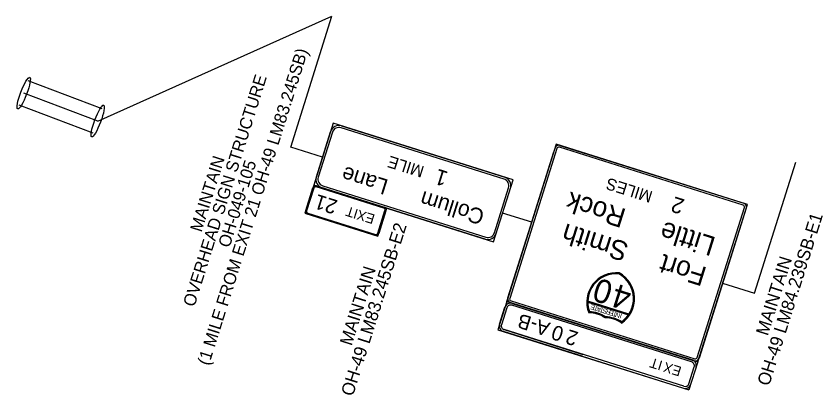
# Model space of a CAD drawing. Extents: x 641128 to 649424, y 422807 to 432853.
# Drawn here: x 644868 to 645659, y 432481 to 432853 of the extents above; entities that cross this region are included whole.
import ezdxf

# ---------------------------------------------------------------- set-up
doc = ezdxf.new("R2010")
doc.units = 0
for name, color, linetype in [('C-TRAF-SYMB', 7, 'Continuous'), ('Default', 7, 'Continuous'), ('R_Dimension', 7, 'Continuous'), ('S_SIGN', 7, 'Continuous')]:
    doc.layers.add(name, color=color, linetype=linetype)

msp = doc.modelspace()

# ---------------------------------------------------------------- linework, layer by layer
at = {"layer": 'C-TRAF-SYMB'}
for p, q in [((644952.5, 432761.81), (644879.93, 432789.25)), ((644947.97, 432749.84), (644875.41, 432777.27)), ((644943.44, 432737.87), (644870.88, 432765.3))]:
    msp.add_line(p, q, dxfattribs=at)
for centre in [(644875.41, 432777.27), (644947.97, 432749.84)]:
    msp.add_ellipse(centre, major_axis=(-5.88, -15.56), ratio=0.180134, dxfattribs=at)
at = {"layer": 'Default'}
for p, q in [((645355.46, 432692.11), (645355.46, 432692.11)), ((645337.13, 432640.29), (645351.02, 432684.42)), ((645337.13, 432640.29), (645337.13, 432640.29))]:
    msp.add_line(p, q, dxfattribs=at)
at = {"layer": 'S_SIGN'}
for p, q in [((644947.97, 432749.84), (645177.77, 432852.82)), ((645178.96, 432747.69), (645159.86, 432687.02)), ((645355.46, 432692.11), (645178.96, 432747.69)), ((645187.24, 432745.08), (645347.19, 432694.72)), ((645187.24, 432745.08), (645347.19, 432694.72)), ((645162.46, 432695.29), (645176.36, 432739.42)), ((645162.46, 432695.29), (645176.36, 432739.42)), ((645178.2, 432738.84), (645164.3, 432694.71)), ((645178.2, 432738.84), (645164.3, 432694.71)), ((645178.2, 432738.84), (645178.2, 432738.84)), ((645178.2, 432738.84), (645178.2, 432738.84)), ((645346.61, 432692.88), (645186.66, 432743.25)), ((645346.61, 432692.88), (645186.66, 432743.25)), ((645397.78, 432727.08), (645349.15, 432572.64)), ((645397.78, 432727.08), (645349.15, 432572.64)), ((645350.31, 432576.32), (645396.62, 432723.41)), ((645350.31, 432576.32), (645396.62, 432723.41)), ((645350.31, 432576.32), (645396.62, 432723.41)), ((645398.46, 432722.83), (645352.15, 432575.74)), ((645398.46, 432722.83), (645352.15, 432575.74)), ((645398.46, 432722.83), (645352.15, 432575.74)), ((645398.46, 432722.83), (645352.15, 432575.74)), ((645585.31, 432668.03), (645397.78, 432727.08)), ((645398.46, 432722.83), (645398.46, 432722.83)), ((645398.46, 432722.83), (645398.46, 432722.83)), ((645581.06, 432667.35), (645400.88, 432724.09)), ((645581.06, 432667.35), (645400.88, 432724.09)), ((645401.46, 432725.93), (645581.64, 432669.19)), ((645401.46, 432725.93), (645581.64, 432669.19)), ((645349.15, 432572.64), (645395.46, 432719.73)), ((645336.36, 432631.44), (645355.46, 432692.11)), ((645346.61, 432692.88), (645346.61, 432692.88)), ((645346.61, 432692.88), (645346.61, 432692.88)), ((645159.86, 432687.02), (645151.17, 432659.44)), ((645152.04, 432662.2), (645158.99, 432684.26)), ((645152.04, 432662.2), (645158.99, 432684.26)), ((645159.91, 432683.97), (645152.96, 432661.91)), ((645159.91, 432683.97), (645152.96, 432661.91)), ((645159.86, 432687.02), (645336.36, 432631.44)), ((645231.56, 432664.44), (645159.86, 432687.02)), ((645159.91, 432683.97), (645159.91, 432683.97)), ((645159.91, 432683.97), (645159.91, 432683.97)), ((645228.51, 432664.39), (645162.33, 432685.23)), ((645228.51, 432664.39), (645162.33, 432685.23)), ((645162.62, 432686.15), (645228.8, 432665.31)), ((645162.62, 432686.15), (645228.8, 432665.31)), ((645328.09, 432634.04), (645168.13, 432684.41)), ((645328.09, 432634.04), (645168.13, 432684.41)), ((645168.71, 432686.25), (645328.66, 432635.88)), ((645168.71, 432686.25), (645168.71, 432686.25)), ((645168.71, 432686.25), (645328.66, 432635.88)), ((645168.71, 432686.25), (645168.71, 432686.25)), ((645337.13, 432640.29), (645351.02, 432684.42)), ((645536.68, 432513.59), (645585.31, 432668.03)), ((645581.06, 432667.35), (645581.06, 432667.35)), ((645581.06, 432667.35), (645581.06, 432667.35)), ((645585.31, 432668.03), (645585.31, 432668.03)), ((645151.17, 432659.44), (645222.88, 432636.86)), ((645220.12, 432637.73), (645153.93, 432658.57)), ((645220.12, 432637.73), (645153.93, 432658.57)), ((645154.22, 432659.49), (645220.41, 432638.65)), ((645154.22, 432659.49), (645154.22, 432659.49)), ((645154.22, 432659.49), (645220.41, 432638.65)), ((645154.22, 432659.49), (645154.22, 432659.49)), ((645222.83, 432639.91), (645229.77, 432661.97)), ((645222.83, 432639.91), (645229.77, 432661.97)), ((645222.88, 432636.86), (645231.56, 432664.44)), ((645230.69, 432661.68), (645223.75, 432639.62)), ((645230.69, 432661.68), (645223.75, 432639.62)), ((645228.51, 432664.39), (645228.51, 432664.39)), ((645228.51, 432664.39), (645228.51, 432664.39)), ((645231.56, 432664.44), (645231.56, 432664.44)), ((645373.68, 432650.55), (645345.2, 432659.52)), ((645536, 432517.85), (645582.32, 432664.93)), ((645536, 432517.85), (645582.32, 432664.93)), ((645584.16, 432664.35), (645537.84, 432517.27)), ((645584.16, 432664.35), (645537.84, 432517.27)), ((645222.83, 432639.91), (645222.83, 432639.91)), ((645222.83, 432639.91), (645222.83, 432639.91)), ((645459.63, 432600.88), (645459.16, 432600.04)), ((645459.63, 432600.88), (645459.16, 432600.04)), ((645459.63, 432600.88), (645459.16, 432600.04)), ((645459.63, 432600.88), (645459.16, 432600.04)), ((645459.53, 432599.92), (645459.63, 432600.88)), ((645459.53, 432599.92), (645459.63, 432600.88)), ((645459.53, 432599.92), (645459.63, 432600.88)), ((645459.53, 432599.92), (645459.63, 432600.88)), ((645349.15, 432572.64), (645340.47, 432545.07)), ((645349.15, 432572.64), (645536.68, 432513.59)), ((645420.85, 432550.07), (645349.15, 432572.64)), ((645533, 432514.75), (645352.83, 432571.49)), ((645353.41, 432573.33), (645533.58, 432516.59)), ((645353.41, 432573.33), (645353.41, 432573.33)), ((645353.41, 432573.33), (645533.58, 432516.59)), ((645353.41, 432573.33), (645353.41, 432573.33)), ((645437.4, 432544.86), (645354.66, 432570.91)), ((645354.66, 432570.91), (645531.17, 432515.33)), ((645354.66, 432570.91), (645531.17, 432515.33)), ((645428.71, 432573.23), (645428.42, 432572.31)), ((645428.71, 432573.23), (645428.42, 432572.31)), ((645428.71, 432573.23), (645428.42, 432572.31)), ((645428.71, 432573.23), (645428.42, 432572.31)), ((645428.42, 432572.31), (645468.84, 432559.58)), ((645428.42, 432572.31), (645468.84, 432559.58)), ((645428.42, 432572.31), (645468.84, 432559.58)), ((645428.42, 432572.31), (645468.84, 432559.58)), ((645428.69, 432572.23), (645468.57, 432559.67)), ((645428.69, 432572.23), (645468.57, 432559.67)), ((645469.13, 432560.5), (645428.71, 432573.23)), ((645469.13, 432560.5), (645428.71, 432573.23)), ((645469.13, 432560.5), (645428.71, 432573.23)), ((645469.13, 432560.5), (645428.71, 432573.23)), ((645469.13, 432560.5), (645428.71, 432573.23)), ((645469.13, 432560.5), (645428.71, 432573.23)), ((645530.59, 432513.49), (645354.09, 432569.07)), ((645429.63, 432562.79), (645429.62, 432561.83)), ((645429.63, 432562.79), (645429.62, 432561.83)), ((645429.63, 432562.79), (645429.62, 432561.83)), ((645429.63, 432562.79), (645429.62, 432561.83)), ((645429.62, 432561.83), (645430.52, 432562.17)), ((645429.62, 432561.83), (645430.52, 432562.17)), ((645429.62, 432561.83), (645430.52, 432562.17)), ((645429.62, 432561.83), (645430.52, 432562.17)), ((645445.75, 432557.72), (645445.74, 432556.76)), ((645445.75, 432557.72), (645445.74, 432556.76)), ((645445.75, 432557.72), (645445.74, 432556.76)), ((645445.75, 432557.72), (645445.74, 432556.76)), ((645445.74, 432556.76), (645446.28, 432557.55)), ((645445.74, 432556.76), (645446.28, 432557.55)), ((645445.74, 432556.76), (645446.28, 432557.55)), ((645445.74, 432556.76), (645446.28, 432557.55)), ((645468.84, 432559.58), (645469.13, 432560.5)), ((645468.84, 432559.58), (645469.13, 432560.5)), ((645468.84, 432559.58), (645469.13, 432560.5)), ((645468.84, 432559.58), (645469.13, 432560.5)), ((645469.13, 432560.5), (645469.13, 432560.5)), ((645469.13, 432560.5), (645469.13, 432560.5)), ((645461.31, 432552.48), (645461.85, 432551.68)), ((645461.31, 432552.48), (645461.85, 432551.68)), ((645461.31, 432552.48), (645461.85, 432551.68)), ((645461.31, 432552.48), (645461.85, 432551.68)), ((645461.85, 432551.68), (645462.4, 432552.47)), ((645461.85, 432551.68), (645462.4, 432552.47)), ((645461.85, 432551.68), (645462.4, 432552.47)), ((645461.85, 432551.68), (645462.4, 432552.47)), ((645340.47, 432545.07), (645528, 432486.01)), ((645346.56, 432545.17), (645423.78, 432520.85)), ((645523.06, 432489.59), (645346.56, 432545.17)), ((645437.4, 432544.86), (645437.4, 432544.86)), ((645423.2, 432519.01), (645528, 432486.01)), ((645536, 432517.85), (645536, 432517.85)), ((645536, 432517.85), (645536, 432517.85)), ((645536.68, 432513.59), (645528, 432486.01))]:
    msp.add_line(p, q, dxfattribs=at)
for points in [[(645168.48, 432714.41), (645137.28, 432724.24), (645177.77, 432852.82)], [(645561, 432590.81), (645592.2, 432580.99), (645632.69, 432709.57)], [(645342.2, 432550.58), (645347.41, 432567.13)], [(645349.25, 432566.55), (645344.04, 432550)], [(645349.25, 432566.55), (645349.25, 432566.55), (645349.25, 432566.55)], [(645423.2, 432519.01), (645345.98, 432543.33)], [(645346.56, 432545.17), (645423.78, 432520.85)], [(645346.56, 432545.17), (645346.56, 432545.17), (645346.56, 432545.17)], [(645527.9, 432492.11), (645533.11, 432508.66)]]:
    msp.add_lwpolyline(points, dxfattribs=at)
for centre, radius, start, end in [((645184.63, 432736.81), 8.67, 72.52135, 162.52135), ((645184.63, 432736.81), 8.67, 72.52135, 162.52135), ((645184.63, 432736.81), 6.75, 72.52135, 162.52135), ((645184.63, 432736.81), 6.75, 72.52135, 162.52135), ((645400.3, 432722.25), 3.86, 72.52135, 162.52135), ((645400.3, 432722.25), 3.86, 72.52135, 162.52135), ((645400.3, 432722.25), 1.93, 72.52135, 162.52135), ((645400.3, 432722.25), 1.93, 72.52135, 162.52135), ((645170.74, 432692.69), 8.67, 162.52134, 252.52134), ((645170.74, 432692.69), 8.67, 162.52134, 252.52134), ((645170.74, 432692.69), 6.75, 162.52134, 252.52134), ((645170.74, 432692.69), 6.75, 162.52134, 252.52134), ((645344.59, 432686.44), 6.75, 342.52134, 72.52135), ((645344.59, 432686.44), 6.75, 342.52134, 72.52135), ((645344.59, 432686.44), 8.67, 342.52134, 72.52135), ((645344.59, 432686.44), 8.67, 342.52134, 72.52135), ((645161.75, 432683.39), 2.89, 72.52135, 162.52135), ((645161.75, 432683.39), 2.89, 72.52135, 162.52135), ((645161.75, 432683.39), 1.93, 72.52135, 162.52135), ((645161.75, 432683.39), 1.93, 72.52135, 162.52135), ((645580.48, 432665.51), 1.93, 342.52134, 72.52135), ((645580.48, 432665.51), 1.93, 342.52134, 72.52135), ((645580.48, 432665.51), 3.86, 342.52134, 72.52135), ((645580.48, 432665.51), 3.86, 342.52134, 72.52135), ((645154.8, 432661.33), 2.89, 162.52134, 252.52134), ((645154.8, 432661.33), 2.89, 162.52134, 252.52134), ((645154.8, 432661.33), 1.93, 162.52134, 252.52134), ((645154.8, 432661.33), 1.93, 162.52134, 252.52134), ((645227.93, 432662.55), 1.93, 342.52134, 72.52135), ((645227.93, 432662.55), 1.93, 342.52134, 72.52135), ((645227.93, 432662.55), 2.89, 342.52134, 72.52135), ((645227.93, 432662.55), 2.89, 342.52134, 72.52135), ((645220.99, 432640.49), 2.89, 252.52134, 342.52134), ((645220.99, 432640.49), 2.89, 252.52134, 342.52134), ((645220.99, 432640.49), 1.93, 252.52134, 342.52134), ((645220.99, 432640.49), 1.93, 252.52134, 342.52134), ((645330.69, 432642.32), 8.67, 252.52134, 342.52134), ((645330.69, 432642.32), 8.67, 252.52134, 342.52134), ((645330.69, 432642.32), 6.75, 252.52134, 342.52134), ((645330.69, 432642.32), 6.75, 252.52134, 342.52134), ((645456.64, 432572.12), 28.91, 84.05832, 200.8524), ((645456.64, 432572.12), 28.91, 84.0583, 200.85241), ((645456.64, 432572.12), 28.91, 84.0583, 200.85241), ((645456.64, 432572.12), 28.91, 84.05832, 200.8524), ((645456.64, 432572.12), 28.91, 84.0583, 200.85241), ((645456.64, 432572.12), 28.91, 84.0583, 200.85241), ((645456.64, 432572.12), 27.95, 84.0583, 200.85241), ((645456.64, 432572.12), 27.95, 84.0583, 200.85241), ((645456.64, 432572.12), 27.95, 84.0583, 200.85241), ((645456.64, 432572.12), 27.95, 84.0583, 200.85241), ((645456.64, 432572.14), 27.95, 84.4508, 177.76811), ((645456.64, 432572.14), 27.95, 84.4508, 177.76811), ((645445.61, 432575.6), 27.95, 304.1903, 60.9844), ((645445.61, 432575.6), 27.95, 304.1903, 60.9844), ((645445.61, 432575.6), 27.95, 304.1903, 60.9844), ((645445.61, 432575.6), 27.95, 304.1903, 60.9844), ((645445.62, 432575.61), 27.95, 327.27459, 60.59192), ((645445.62, 432575.61), 27.95, 327.27459, 60.59192), ((645445.61, 432575.6), 28.91, 304.1903, 60.9844), ((645445.61, 432575.6), 28.91, 304.1903, 60.9844), ((645445.61, 432575.6), 28.91, 304.1903, 60.9844), ((645445.61, 432575.6), 28.91, 304.1903, 60.9844), ((645445.61, 432575.6), 28.91, 304.1903, 60.9844), ((645445.61, 432575.6), 28.91, 304.1903, 60.9844), ((645352.93, 432565.39), 5.78, 72.5214, 162.52161), ((645353.98, 432575.16), 3.86, 162.52134, 252.52134), ((645353.98, 432575.16), 3.86, 162.52134, 252.52134), ((645353.98, 432575.16), 1.93, 162.52134, 252.52134), ((645353.98, 432575.16), 1.93, 162.52134, 252.52134), ((645456.64, 432572.12), 27.95, 179.78462, 199.5255), ((645456.64, 432572.12), 27.95, 179.78462, 199.5255), ((645352.93, 432565.39), 3.86, 72.5214, 162.52161), ((645429.37, 432532.92), 29.88, 55.53044, 89.51229), ((645429.37, 432532.92), 29.88, 55.53044, 89.51229), ((645429.37, 432532.92), 29.88, 55.53044, 89.51229), ((645429.37, 432532.92), 29.88, 55.53044, 89.51229), ((645429.3, 432532.92), 29.88, 55.94687, 88.0821), ((645429.3, 432532.92), 29.88, 55.94687, 88.0821), ((645429.37, 432532.92), 28.91, 55.53043, 89.51229), ((645429.37, 432532.92), 28.91, 55.53044, 89.51229), ((645429.37, 432532.92), 28.91, 55.53044, 89.51229), ((645429.37, 432532.92), 28.91, 55.53043, 89.51229), ((645429.37, 432532.92), 28.91, 55.53044, 89.51229), ((645429.37, 432532.92), 28.91, 55.53044, 89.51229), ((645445.49, 432527.84), 28.91, 55.53043, 89.51229), ((645445.49, 432527.84), 28.91, 55.53044, 89.51229), ((645445.49, 432527.84), 28.91, 55.53044, 89.51229), ((645445.49, 432527.84), 28.91, 55.53043, 89.51229), ((645445.49, 432527.84), 28.91, 55.53044, 89.51229), ((645445.49, 432527.84), 28.91, 55.53044, 89.51229), ((645445.49, 432527.84), 29.88, 55.53044, 89.51229), ((645445.49, 432527.84), 29.88, 55.53044, 89.51229), ((645445.49, 432527.84), 29.88, 55.53044, 89.51229), ((645445.49, 432527.84), 29.88, 55.53044, 89.51229), ((645445.55, 432527.8), 29.88, 56.96062, 89.09585), ((645445.55, 432527.8), 29.88, 56.96062, 89.09585), ((645445.61, 432575.6), 27.95, 305.51718, 325.25806), ((645445.61, 432575.6), 27.95, 305.51718, 325.25806), ((645347.72, 432548.85), 5.78, 162.52134, 252.52155), ((645347.72, 432548.85), 3.86, 162.52134, 252.52155), ((645529.43, 432509.81), 5.78, 342.52119, 72.5214), ((645534.16, 432518.43), 3.86, 252.52134, 342.52134), ((645534.16, 432518.43), 3.86, 252.52134, 342.52134), ((645534.16, 432518.43), 1.93, 252.52134, 342.52134), ((645534.16, 432518.43), 1.93, 252.52134, 342.52134), ((645529.43, 432509.81), 3.86, 342.52119, 72.5214), ((645524.22, 432493.27), 5.78, 252.52155, 342.52119), ((645524.22, 432493.27), 3.86, 252.52155, 342.52119)]:
    msp.add_arc(centre, radius, start, end, dxfattribs=at)

# ---------------------------------------------------------------- texts
at = {"layer": 'R_Dimension'}
for s, height, p in [('(1 MILE FROM EXIT 21 OH-49 LM83.245SB)', 12, (645057.04, 432509.32)), ('OVERHEAD SIGN STRUCTURE', 12, (645042.83, 432566.84)), ('MAINTAIN', 12, (645049.78, 432640.21)), ('OH-049-105', 12, (645077.28, 432624.9)), ('OH-49 LM84.239SB-E1', 12.5, (645606.54, 432489.19)), ('OH-49 LM83.245SB-E2', 12.5, (645198.23, 432479.12)), ('MAINTAIN', 12.5, (645605.22, 432538.46)), ('MAINTAIN', 12.5, (645197.01, 432528.69))]:
    msp.add_text(s, height=height, rotation=72.52134, dxfattribs=at).set_placement(p)
at = {"layer": 'S_SIGN'}
for s, height, rotation, p in [('MILE', 11.565, 162.52134, (645269.14, 432705.15)), ('Lane', 15.42, 162.52134, (645234.03, 432691.95)), ('1 ', 15.42, 162.52134, (645292.67, 432699.76)), ('MILES', 11.565, 162.52134, (645493.21, 432680.49)), ('21', 14.457, 162.52134, (645184.21, 432671.77)), ('Collum', 15.42, 162.52134, (645328.52, 432662.2)), ('Rock', 19.276, 162.52134, (645467.44, 432663.09)), ('2', 15.42, 162.52134, (645524.61, 432672.62)), ('EXIT', 9.638, 162.52134, (645220.62, 432657.78)), ('Little', 19.276, 162.52134, (645555.35, 432635.41)), ('Smith', 19.276, 162.52134, (645470.02, 432629.94)), ('Fort', 19.276, 162.52134, (645546.61, 432605.83)), ('0', 23.13, 162.52134, (645455.07, 432591.2)), ('0', 23.13, 162.52134, (645455.07, 432591.2)), ('4', 23.13, 162.52134, (645473.34, 432585.45)), ('4', 23.13, 162.52134, (645473.34, 432585.45)), ('E', 4.82, 162.52134, (645436.29, 432568.82)), ('E', 4.82, 162.52134, (645436.29, 432568.82)), ('T', 4.82, 162.52134, (645439.37, 432567.86)), ('T', 4.82, 162.52134, (645439.37, 432567.86)), ('A', 4.82, 162.52134, (645442.5, 432566.87)), ('A', 4.82, 162.52134, (645442.5, 432566.87)), ('T', 4.82, 162.52134, (645445.06, 432566.06)), ('T', 4.82, 162.52134, (645445.06, 432566.06)), ('S', 4.82, 162.52134, (645448.35, 432565.03)), ('S', 4.82, 162.52134, (645448.35, 432565.03)), ('R', 4.82, 162.52134, (645451.64, 432563.99)), ('R', 4.82, 162.52134, (645451.64, 432563.99)), ('E', 4.82, 162.52134, (645454.71, 432563.02)), ('E', 4.82, 162.52134, (645454.71, 432563.02)), ('T', 4.82, 162.52134, (645457.79, 432562.05)), ('T', 4.82, 162.52134, (645457.79, 432562.05)), ('A-B', 14.16, 162.621, (645392.69, 432551.71)), ('N', 4.82, 162.52134, (645461.08, 432561.02)), ('N', 4.82, 162.52134, (645461.08, 432561.02)), ('I', 4.82, 162.52134, (645462.69, 432560.51)), ('I', 4.82, 162.52134, (645462.69, 432560.51)), ('0', 14.46, 162.52134, (645406.28, 432546.9)), ('2', 14.46, 162.52134, (645420.35, 432542.48)), ('T', 9.64, 162.52134, (645499.06, 432515.34)), ('I', 9.64, 162.52134, (645502.83, 432514.15)), ('X', 9.64, 162.52134, (645513.09, 432510.92)), ('E', 9.64, 162.52134, (645521.4, 432508.3))]:
    msp.add_text(s, height=height, rotation=rotation, dxfattribs=at).set_placement(p)

doc.saveas('drawing.dxf')
